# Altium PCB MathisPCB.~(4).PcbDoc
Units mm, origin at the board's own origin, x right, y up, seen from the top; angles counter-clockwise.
Board outline 17.02 x 14.1 mm, 2 copper layers (Top Layer, Bottom Layer); 8 components, 10 nets, 25 pads, 1 vias.
Unrouted connection lines stored in the file: 15.
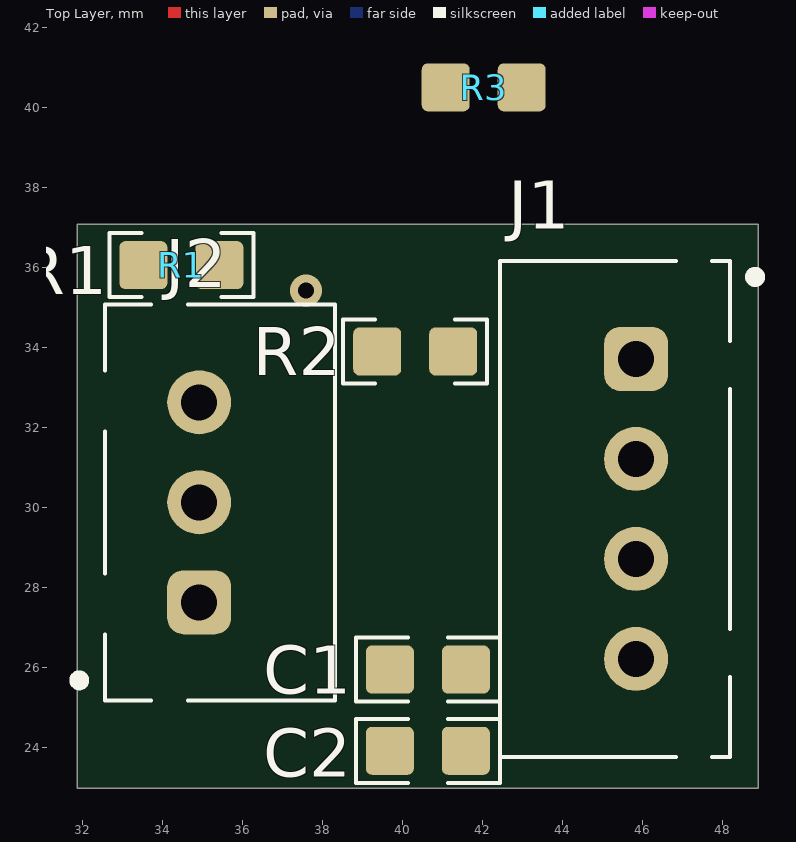
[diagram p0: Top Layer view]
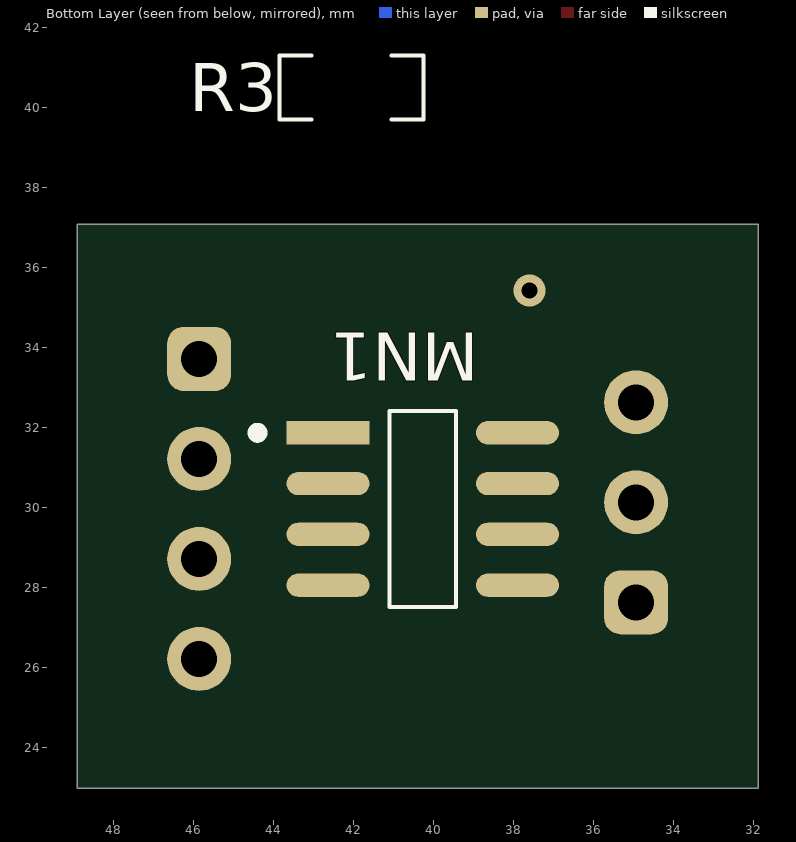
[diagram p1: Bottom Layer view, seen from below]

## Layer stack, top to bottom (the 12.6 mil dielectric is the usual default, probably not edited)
Top Solder: solder mask 0.0102, Solder Resist, Dk 3.5
Top Layer: signal copper 0.0356
Dielectric 1: dielectric 0.32, FR-4, Dk 4.8
Bottom Layer: signal copper 0.0356
Bottom Solder: solder mask 0.0102, Solder Resist, Dk 3.5

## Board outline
31.877,22.987 31.877,37.084 48.895,37.084 48.895,22.987

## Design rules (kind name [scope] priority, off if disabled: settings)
Clearance [All] p1: gap=0.254 ignorepadtopadclearanceinfootprint=FALSE except(0: Arc-Hole Track-Hole SMDPad-Hole THPad-Hole Via-Hole Fill-Hole Poly-Hole Region-Hole Text-Hole)
PolygonConnect [All] p1: connectstyle=Relief reliefconductorwidth=0.254 reliefentries=4 polygonreliefangle="90 Angle" airgapwidth=0.254
RoutingVias [All] p1: holewidth=0.711 width=1.27 viastyle="Through Hole" minholewidth=0.711 minwidth=1.27 maxholewidth=0.711 maxwidth=1.27
SolderMaskExpansion [All] p1: expansion=0.102 istentingtop=FALSE
Width [All] p1: maxlimit=0.254 minlimit=0.254 preferedwidth=0.254
30 further rules are at their usual default settings.

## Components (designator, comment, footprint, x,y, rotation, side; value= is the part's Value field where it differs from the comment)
C1 "MCU0805R104KCT" CAP_0805 40.64,25.908 r0 top value=100nF
C2 "GRM21BR71H105KA12L" CAP_0805 40.64,23.876 r0 top value=1uF
J1 "B4B-XH-A(LF)(SN)" B4B-XH-A 45.847,29.972 r270 top
J2 "B3B-XH-A(LF)(SN)" B3B-XH-A 34.925,30.139 r90 top
MN1 "CAP1203-1-SN" FP-C04-057-SN-IPC_B 40.259,29.972 r180 bottom
R1 "CRCW08054K70FKEA" RES_0805#1 34.478,36.068 r180 top
R2 "CRCW08054K70FKEA" RES_0805#1 40.325,33.909 r180 top
R3 "CRCW08054K70FKEA" RES_0805#2 42.037,40.513 r180 bottom

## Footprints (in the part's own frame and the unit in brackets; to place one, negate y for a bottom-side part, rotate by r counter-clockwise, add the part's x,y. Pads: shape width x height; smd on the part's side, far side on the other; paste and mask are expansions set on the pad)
B3B-XH-A [mm] "JST XH 3pts 2.5mm"
  rrect50% 1.6x1.6 hole 0.9: 1(-2.5,0)
  round 1.6 hole 0.9: 2(0,0) 3(2.5,0)
  silkscreen extent -4.95,-3.4 4.95,3.1, body extent -4.95,-3.41 4.95,2.35, height 7
B4B-XH-A [mm] "JST XH 4pts 2.5mm"
  rrect50% 1.6x1.6 hole 0.9: 1(-3.75,0)
  round 1.6 hole 0.9: 2(-1.25,0) 3(1.25,0) 4(3.75,0)
  silkscreen extent -6.2,-3.4 6.2,3.08, body extent -6.2,-3.37 6.2,2.38, height 7
CAP_0805 [mm] "Capacitor 0805"
  rrect25% 1.2x1.2 smd: 1(-0.95,0.05) 2(0.95,0.05)
  silkscreen extent -1.8,-0.75 1.8,0.85, body extent -1,-0.58 1,0.67, height 0.81
FP-C04-057-SN-IPC_B [mm]
  rect 2.077x0.582 smd paste+0 mask+0: 1(-2.368,1.905)
  rrect100% 2.077x0.582 smd paste+0 mask+0: 2(-2.368,0.635) 3(-2.368,-0.635) 4(-2.368,-1.905) 5(2.368,-1.905) 6(2.368,-0.635) 7(2.368,0.635) 8(2.368,1.905)
  silkscreen extent -4.26,-2.45 0.83,2.45, body extent -3,-2.45 3,2.45, height 1.75
RES_0805#1 [mm] "0805 resistors"
  rrect25% 1.2x1.2 smd: 1(-0.95,0) 2(0.95,0)
  silkscreen extent -1.8,-0.8 1.8,0.8, body extent -1,-0.6 1,0.6, height 0.55
RES_0805#2 [mm] "0805 resistors"
  rrect25% 1.2x1.2 smd far side: 1(-0.95,0) 2(0.95,0)
  silkscreen extent -1.8,-0.8 1.8,0.8, body extent -1,-0.6 1,0.6, height 0.55

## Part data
C1: library part U0805R104KCT-1, "Cap Ceramic 0.1uF 50V X7R ±10% SMD 0805 125°C T/R", Case Code (Imperial)=0805, Case Code (Metric)=2012, Dielectric=X7R, Max Operating Temperature=125°C, Min Operating Temperature=-55°C, Tolerance=10%, Voltage Rating=50V
C2: library part GRM21BR71H105KA12L-1, "0805 1 uF 50 V ±10% Tolerance X7R Multilayer Ceramic Chip Capacitor", Case Code (Imperial)=0805, Case Code (Metric)=2012, Dielectric=X7R, Max Operating Temperature=125°C, Min Operating Temperature=-55°C, Package Quantity=1, Tolerance=10%, Voltage=50V
J1: library part CMP-047-000046-2, "JST Connector Header, XH Series, 4 Positions, 2.5mm Pitch Through Hole Crimp Top Entry Shrouded Header", Color=Natural, Contact Resistance=20mR, Current Rating=3A, Flammability Rating="UL94 V-0", Housing Color=White, Insulation Resistance=1GR, Manufacturer=JST, Max Operating Temperature=85°C, Max Voltage Rating (AC)=250V, Min Operating Temperature=-25°C, Package Quantity=500
J2: library part CMP-047-000044-2, "JST Connector Header, XH Series, 3 Positions, 2.50mm, Through Hole, Press-Fit, Solder, Natural", Manufacturer=JST
MN1: library part CMP-000015-1, "Touch Sensor Capacitive 3 Key 3V to 5.5V SMD 8-Pin SOIC Tube", Case/Package=SOIC, Max Operating Temperature=125°C, Min Operating Temperature=-40°C, Operating Supply Current=750uA
R1 R2 R3: library part CMP-079-000100-3, "Resistor Thick Film 0805 4.7K Ohm 1% ±100ppm/°C Molded SMD SMD Paper T/R", Resistance=4.7K

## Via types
v1: diameter 0.8, hole 0.4, Top Layer to Bottom Layer, 1 vias

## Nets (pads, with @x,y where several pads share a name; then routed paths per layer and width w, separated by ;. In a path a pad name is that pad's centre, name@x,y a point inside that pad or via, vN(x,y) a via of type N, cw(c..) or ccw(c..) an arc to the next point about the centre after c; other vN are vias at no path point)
+5V: C1.2 C2.2 J1.4 MN1.4
GND: C1.1 C2.1 J1.3 MN1.1 MN1.5
NetJ1_1: J1.1 MN1.3
NetJ1_2: J1.2 MN1.2
NetJ2_1: J2.1 R1.2
NetJ2_2: J2.2 R2.2
NetJ2_3: J2.3 R3.1
NetMN1_6: MN1.6 R3.2
NetMN1_7: MN1.7 R2.1
NetMN1_8: MN1.8 R1.1
copper on no net:
  other v1: 37.592,35.433

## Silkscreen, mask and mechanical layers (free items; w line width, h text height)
Board Shape:
  the board outline again, w0.254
